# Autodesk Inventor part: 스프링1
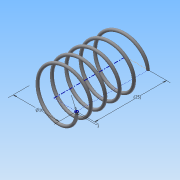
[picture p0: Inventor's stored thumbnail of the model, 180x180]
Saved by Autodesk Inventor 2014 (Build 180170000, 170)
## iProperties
Created: 2015-06
Part Number: 스프링1
Material: 강철, 연강
Document SubType Name: Modeling
Designer: Administrator
Density: 7.86 g/cm^3
Appearance: 강철
Mass: 1.52988 g
Surface Area: 7.87024 cm^2
Volume: 0.194641 cm^3
Author: Administrator
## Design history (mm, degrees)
sketch "스케치1"
  geometry: L1 (0, 0)-(8, 0); L2 (8, 0)-(8, 14.5); L3 (8, 14.5)-(0, 14.5); L4 (0, 14.5)-(0, 0); C1 r 0.5 at (8, 0)
  constraints: 8 end point, 2 parallel, 1 centre point, 1 coincident, 1 horizontal, 1 perpendicular
  dimensions: "d0" = 14.5 distance of L1.end L2.end (derived); "d1" = 16 diameter of L2 L4; "d2" = 1 diameter of C1
feature "코일1" sketch "스케치1" pitch "d3" = 10; turns "d5" = 5; dims "d4" = 14.5 (= d0), "d6" = 0, angle "d7" = 90 deg, angle "d8" = 90 deg, "d9" = 0, "d10" = 0
sketch "스케치2"
  geometry: L1 (-8.5, 0)-(-7.5, 0) reference; 1 further point
  constraints: 1 horizontal alignment
extrude "돌출1" cut sketch "스케치2" stored distance "d11" = 10; taper "d12" = 0 deg
node "작업 평면1"
sketch "스케치3"
  geometry: L1 (-7.5, 0)-(-8.5, 0) reference; 1 further point
  constraints: 1 horizontal alignment
extrude "돌출2" cut sketch "스케치3" stored distance "d14" = 10; taper "d15" = 0 deg
node "솔리드1"
node "절단 모서리 투영1"
node "절단 모서리 투영2"
other parameters: "d13" = 14.5 (= d0)
